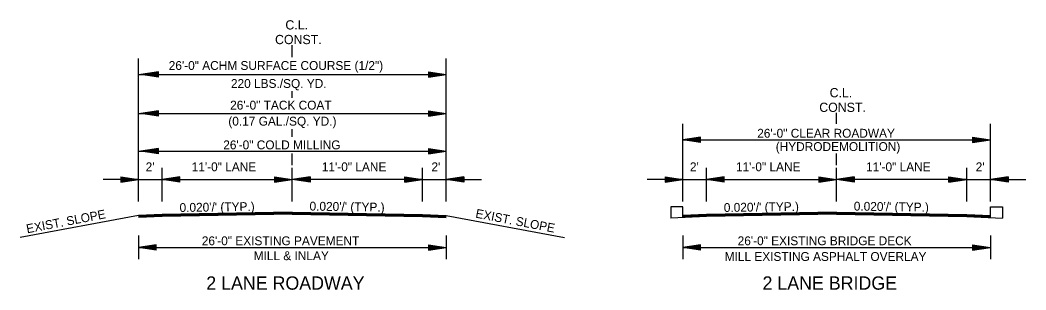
# Model space of a CAD drawing. Extents: x 549600 to 1930787, y -1955432 to 596640.
# Drawn here: x 549615 to 550465, y -1947150 to -1946922 of the extents above; entities that cross this region are included whole.
import ezdxf

# ---------------------------------------------------------------- set-up
doc = ezdxf.new("R2010")
doc.units = 0
doc.layers.add('R_Border', color=7, linetype='Continuous')
doc.layers.add('S_AREA_CALC', color=7, linetype='Continuous')

msp = doc.modelspace()

# ---------------------------------------------------------------- linework, layer by layer
at = {"layer": 'R_Border'}
for p, q in [((549974.89, -1947056.39), (550004.89, -1947056.39)), ((550434.89, -1947056.39), (550464.89, -1947056.39)), ((550164.72, -1947079.69), (550164.71, -1947089.07)), ((550174.89, -1947079.69), (550164.72, -1947079.69)), ((550174.89, -1947088.49), (550174.89, -1947079.69)), ((550434.89, -1947088.49), (550434.89, -1947079.69)), ((550434.89, -1947079.69), (550445.05, -1947079.69)), ((550445.05, -1947079.69), (550445.07, -1947089.07))]:
    msp.add_line(p, q, dxfattribs=at)
at = {"layer": 'S_AREA_CALC'}
for p, q in [((549844.89, -1946953.23), (549844.89, -1946942.86)), ((549714.89, -1947075.21), (549714.89, -1946954.34)), ((549974.89, -1947075.21), (549974.89, -1946954.34)), ((549714.89, -1946967.71), (549974.89, -1946967.71)), ((549731.89, -1946965.46), (549716.89, -1946967.71)), ((549731.89, -1946969.96), (549716.89, -1946967.71)), ((549731.89, -1946965.84), (549719.39, -1946967.71)), ((549731.89, -1946969.59), (549719.39, -1946967.71)), ((549731.89, -1946966.22), (549721.97, -1946967.71)), ((549731.89, -1946969.2), (549721.97, -1946967.71)), ((549731.89, -1946966.59), (549724.47, -1946967.71)), ((549731.89, -1946968.83), (549724.47, -1946967.71)), ((549731.89, -1946966.98), (549727.01, -1946967.71)), ((549731.89, -1946968.44), (549727.01, -1946967.71)), ((549731.89, -1946967.36), (549729.52, -1946967.71)), ((549731.89, -1946968.06), (549729.52, -1946967.71)), ((549731.89, -1946969.96), (549731.89, -1946965.46)), ((549959.89, -1946965.46), (549974.89, -1946967.71)), ((549959.89, -1946965.46), (549959.89, -1946969.96)), ((549959.89, -1946965.84), (549972.38, -1946967.71)), ((549959.89, -1946966.22), (549969.8, -1946967.71)), ((549959.89, -1946966.59), (549967.31, -1946967.71)), ((549959.89, -1946966.98), (549964.76, -1946967.71)), ((549959.89, -1946967.36), (549962.26, -1946967.71)), ((549959.89, -1946969.96), (549974.89, -1946967.71)), ((549959.89, -1946968.45), (549964.76, -1946967.71)), ((549959.89, -1946969.2), (549969.8, -1946967.71)), ((549959.89, -1946969.59), (549972.38, -1946967.71)), ((549959.89, -1946968.83), (549967.31, -1946967.71)), ((549959.89, -1946968.06), (549962.26, -1946967.71)), ((549844.89, -1946987.45), (549844.89, -1946981.92)), ((549714.89, -1947000.68), (549974.89, -1947000.68)), ((549731.89, -1946998.43), (549716.89, -1947000.68)), ((549731.89, -1947002.93), (549716.89, -1947000.68)), ((549731.89, -1946998.8), (549719.39, -1947000.68)), ((549731.89, -1947002.55), (549719.39, -1947000.68)), ((549731.89, -1946999.19), (549721.97, -1947000.68)), ((549731.89, -1947002.17), (549721.97, -1947000.68)), ((549731.89, -1946999.56), (549724.47, -1947000.68)), ((549731.89, -1947001.8), (549724.47, -1947000.68)), ((549731.89, -1946999.94), (549727.01, -1947000.68)), ((549731.89, -1947001.41), (549727.01, -1947000.68)), ((549731.89, -1947000.33), (549729.52, -1947000.68)), ((549731.89, -1947001.03), (549729.52, -1947000.68)), ((549731.89, -1947002.93), (549731.89, -1946998.43)), ((549959.89, -1946998.43), (549974.89, -1947000.68)), ((549959.89, -1946998.43), (549959.89, -1947002.93)), ((549959.89, -1946998.8), (549972.38, -1947000.68)), ((549959.89, -1946999.19), (549969.8, -1947000.68)), ((549959.89, -1946999.56), (549967.31, -1947000.68)), ((549959.89, -1946999.95), (549964.76, -1947000.68)), ((549959.89, -1947000.33), (549962.26, -1947000.68)), ((549959.89, -1947002.93), (549974.89, -1947000.68)), ((549959.89, -1947001.41), (549964.76, -1947000.68)), ((549959.89, -1947002.17), (549969.8, -1947000.68)), ((549959.89, -1947002.55), (549972.38, -1947000.68)), ((549959.89, -1947001.8), (549967.31, -1947000.68)), ((549959.89, -1947001.03), (549962.26, -1947000.68)), ((550304.89, -1947009.43), (550304.89, -1947000.13)), ((549974.89, -1947075.21), (549974.89, -1947009.48)), ((550174.89, -1947075.21), (550174.89, -1947009.48)), ((550434.89, -1947075.21), (550434.89, -1947009.48)), ((549844.89, -1947020.42), (549844.89, -1947014)), ((550189.89, -1947020.6), (550174.89, -1947022.85)), ((550189.89, -1947020.97), (550177.39, -1947022.85)), ((550189.89, -1947021.36), (550179.97, -1947022.85)), ((550189.89, -1947021.73), (550182.47, -1947022.85)), ((550189.89, -1947025.1), (550189.89, -1947020.6)), ((550419.89, -1947020.6), (550434.89, -1947022.85)), ((550419.89, -1947020.6), (550419.89, -1947025.1)), ((550419.89, -1947020.97), (550432.38, -1947022.85)), ((550419.89, -1947021.36), (550429.8, -1947022.85)), ((550419.89, -1947021.73), (550427.31, -1947022.85)), ((550174.89, -1947022.85), (550432.89, -1947022.85)), ((550189.89, -1947025.1), (550174.89, -1947022.85)), ((550189.89, -1947024.72), (550177.39, -1947022.85)), ((550189.89, -1947024.34), (550179.97, -1947022.85)), ((550189.89, -1947023.97), (550182.47, -1947022.85)), ((550189.89, -1947022.11), (550185.01, -1947022.85)), ((550189.89, -1947023.58), (550185.01, -1947022.85)), ((550189.89, -1947022.5), (550187.52, -1947022.85)), ((550189.89, -1947023.2), (550187.52, -1947022.85)), ((550419.89, -1947022.12), (550424.76, -1947022.85)), ((550419.89, -1947022.5), (550422.26, -1947022.85)), ((550419.89, -1947025.1), (550434.89, -1947022.85)), ((550419.89, -1947023.58), (550424.76, -1947022.85)), ((550419.89, -1947024.34), (550429.8, -1947022.85)), ((550419.89, -1947024.72), (550432.38, -1947022.85)), ((550419.89, -1947023.97), (550427.31, -1947022.85)), ((550419.89, -1947023.2), (550422.26, -1947022.85)), ((549714.89, -1947032.65), (549974.89, -1947032.65)), ((549731.89, -1947030.4), (549716.89, -1947032.65)), ((549731.89, -1947034.9), (549716.89, -1947032.65)), ((549731.89, -1947030.78), (549719.39, -1947032.65)), ((549731.89, -1947034.53), (549719.39, -1947032.65)), ((549731.89, -1947031.16), (549721.97, -1947032.65)), ((549731.89, -1947034.14), (549721.97, -1947032.65)), ((549731.89, -1947031.53), (549724.47, -1947032.65)), ((549731.89, -1947033.77), (549724.47, -1947032.65)), ((549731.89, -1947031.92), (549727.01, -1947032.65)), ((549731.89, -1947033.38), (549727.01, -1947032.65)), ((549731.89, -1947032.3), (549729.52, -1947032.65)), ((549731.89, -1947033), (549729.52, -1947032.65)), ((549731.89, -1947034.9), (549731.89, -1947030.4)), ((549844.89, -1947044.37), (549844.89, -1947034.5)), ((549959.89, -1947030.4), (549974.89, -1947032.65)), ((549959.89, -1947030.4), (549959.89, -1947034.9)), ((549959.89, -1947030.78), (549972.38, -1947032.65)), ((549959.89, -1947031.16), (549969.8, -1947032.65)), ((549959.89, -1947031.53), (549967.31, -1947032.65)), ((549959.89, -1947031.92), (549964.76, -1947032.65)), ((549959.89, -1947032.3), (549962.26, -1947032.65)), ((549959.89, -1947034.9), (549974.89, -1947032.65)), ((549959.89, -1947033.39), (549964.76, -1947032.65)), ((549959.89, -1947034.14), (549969.8, -1947032.65)), ((549959.89, -1947034.53), (549972.38, -1947032.65)), ((549959.89, -1947033.77), (549967.31, -1947032.65)), ((549959.89, -1947033), (549962.26, -1947032.65)), ((550304.89, -1947044.37), (550304.89, -1947034.5)), ((549734.89, -1947075.21), (549734.89, -1947046.49)), ((549844.89, -1947075.04), (549844.89, -1947046.49)), ((549954.89, -1947075.21), (549954.89, -1947046.49)), ((550194.89, -1947075.21), (550194.89, -1947046.49)), ((550304.89, -1947075.04), (550304.89, -1947046.49)), ((550414.89, -1947075.21), (550414.89, -1947046.49)), ((549699.89, -1947054.14), (549714.89, -1947056.39)), ((549699.89, -1947054.14), (549699.89, -1947058.64)), ((549699.89, -1947054.51), (549712.38, -1947056.39)), ((549699.89, -1947054.89), (549709.8, -1947056.39)), ((549699.89, -1947055.27), (549707.31, -1947056.39)), ((549699.89, -1947055.66), (549704.76, -1947056.39)), ((549749.89, -1947054.14), (549734.89, -1947056.39)), ((549749.89, -1947054.51), (549737.39, -1947056.39)), ((549749.89, -1947054.89), (549739.97, -1947056.39)), ((549749.89, -1947055.27), (549742.47, -1947056.39)), ((549749.89, -1947055.65), (549745.01, -1947056.39)), ((549749.89, -1947058.64), (549749.89, -1947054.14)), ((549829.89, -1947054.14), (549844.89, -1947056.39)), ((549829.89, -1947054.14), (549829.89, -1947058.64)), ((549829.89, -1947054.51), (549842.38, -1947056.39)), ((549829.89, -1947054.89), (549839.8, -1947056.39)), ((549829.89, -1947055.27), (549837.31, -1947056.39)), ((549829.89, -1947055.66), (549834.76, -1947056.39)), ((549859.89, -1947054.14), (549844.89, -1947056.39)), ((549859.89, -1947054.51), (549847.39, -1947056.39)), ((549859.89, -1947054.89), (549849.97, -1947056.39)), ((549859.89, -1947055.27), (549852.47, -1947056.39)), ((549859.89, -1947055.66), (549855.01, -1947056.39)), ((549859.89, -1947054.14), (549859.89, -1947058.64)), ((549939.89, -1947054.14), (549954.89, -1947056.39)), ((549939.89, -1947058.64), (549939.89, -1947054.14)), ((549939.89, -1947054.51), (549952.38, -1947056.39)), ((549939.89, -1947054.89), (549949.8, -1947056.39)), ((549939.89, -1947055.27), (549947.31, -1947056.39)), ((549939.89, -1947055.65), (549944.76, -1947056.39)), ((549989.89, -1947054.14), (549974.89, -1947056.39)), ((549989.89, -1947054.51), (549977.39, -1947056.39)), ((549989.89, -1947054.89), (549979.97, -1947056.39)), ((549989.89, -1947055.27), (549982.47, -1947056.39)), ((549989.89, -1947055.66), (549985.01, -1947056.39)), ((549989.89, -1947054.14), (549989.89, -1947058.64)), ((550159.89, -1947054.14), (550174.89, -1947056.39)), ((550159.89, -1947054.14), (550159.89, -1947058.64)), ((550159.89, -1947054.51), (550172.38, -1947056.39)), ((550159.89, -1947054.89), (550169.8, -1947056.39)), ((550159.89, -1947055.27), (550167.31, -1947056.39)), ((550159.89, -1947055.66), (550164.76, -1947056.39)), ((550209.89, -1947054.14), (550194.89, -1947056.39)), ((550209.89, -1947054.51), (550197.39, -1947056.39)), ((550209.89, -1947054.89), (550199.97, -1947056.39)), ((550209.89, -1947055.27), (550202.47, -1947056.39)), ((550209.89, -1947055.65), (550205.01, -1947056.39)), ((550209.89, -1947058.64), (550209.89, -1947054.14)), ((550289.89, -1947054.14), (550304.89, -1947056.39)), ((550289.89, -1947054.14), (550289.89, -1947058.64)), ((550289.89, -1947054.51), (550302.38, -1947056.39)), ((550289.89, -1947054.89), (550299.8, -1947056.39)), ((550289.89, -1947055.27), (550297.31, -1947056.39)), ((550289.89, -1947055.66), (550294.76, -1947056.39)), ((550319.89, -1947054.14), (550304.89, -1947056.39)), ((550319.89, -1947054.51), (550307.39, -1947056.39)), ((550319.89, -1947054.89), (550309.97, -1947056.39)), ((550319.89, -1947055.27), (550312.47, -1947056.39)), ((550319.89, -1947055.66), (550315.01, -1947056.39)), ((550319.89, -1947054.14), (550319.89, -1947058.64)), ((550399.89, -1947054.14), (550414.89, -1947056.39)), ((550399.89, -1947058.64), (550399.89, -1947054.14)), ((550399.89, -1947054.51), (550412.38, -1947056.39)), ((550399.89, -1947054.89), (550409.8, -1947056.39)), ((550399.89, -1947055.27), (550407.31, -1947056.39)), ((550399.89, -1947055.65), (550404.76, -1947056.39)), ((550449.89, -1947054.14), (550434.89, -1947056.39)), ((550449.89, -1947054.51), (550437.39, -1947056.39)), ((550449.89, -1947054.89), (550439.97, -1947056.39)), ((550449.89, -1947055.27), (550442.47, -1947056.39)), ((550449.89, -1947055.66), (550445.01, -1947056.39)), ((550449.89, -1947054.14), (550449.89, -1947058.64)), ((549714.89, -1947056.39), (549684.89, -1947056.39)), ((549699.89, -1947056.03), (549702.26, -1947056.39)), ((549699.89, -1947058.64), (549714.89, -1947056.39)), ((549699.89, -1947057.12), (549704.76, -1947056.39)), ((549699.89, -1947057.88), (549709.8, -1947056.39)), ((549699.89, -1947058.26), (549712.38, -1947056.39)), ((549699.89, -1947057.5), (549707.31, -1947056.39)), ((549699.89, -1947056.74), (549702.26, -1947056.39)), ((549714.89, -1947056.39), (549734.89, -1947056.39)), ((549749.89, -1947058.64), (549734.89, -1947056.39)), ((549734.89, -1947056.39), (549844.89, -1947056.39)), ((549749.89, -1947058.26), (549737.39, -1947056.39)), ((549749.89, -1947057.88), (549739.97, -1947056.39)), ((549749.89, -1947057.5), (549742.47, -1947056.39)), ((549749.89, -1947057.11), (549745.01, -1947056.39)), ((549749.89, -1947056.03), (549747.52, -1947056.39)), ((549749.89, -1947056.74), (549747.52, -1947056.39)), ((549829.89, -1947056.03), (549832.26, -1947056.39)), ((549829.89, -1947058.64), (549844.89, -1947056.39)), ((549829.89, -1947057.12), (549834.76, -1947056.39)), ((549829.89, -1947057.88), (549839.8, -1947056.39)), ((549829.89, -1947058.26), (549842.38, -1947056.39)), ((549829.89, -1947057.5), (549837.31, -1947056.39)), ((549829.89, -1947056.74), (549832.26, -1947056.39)), ((549954.89, -1947056.39), (549844.89, -1947056.39)), ((549859.89, -1947058.64), (549844.89, -1947056.39)), ((549859.89, -1947058.26), (549847.39, -1947056.39)), ((549859.89, -1947057.88), (549849.97, -1947056.39)), ((549859.89, -1947057.5), (549852.47, -1947056.39)), ((549859.89, -1947057.12), (549855.01, -1947056.39)), ((549859.89, -1947056.03), (549857.52, -1947056.39)), ((549859.89, -1947056.74), (549857.52, -1947056.39)), ((549939.89, -1947056.03), (549942.26, -1947056.39)), ((549939.89, -1947058.64), (549954.89, -1947056.39)), ((549939.89, -1947057.11), (549944.76, -1947056.39)), ((549939.89, -1947057.88), (549949.8, -1947056.39)), ((549939.89, -1947058.26), (549952.38, -1947056.39)), ((549939.89, -1947057.5), (549947.31, -1947056.39)), ((549939.89, -1947056.74), (549942.26, -1947056.39)), ((549954.89, -1947056.39), (549974.89, -1947056.39)), ((549989.89, -1947058.64), (549974.89, -1947056.39)), ((549989.89, -1947058.26), (549977.39, -1947056.39)), ((549989.89, -1947057.88), (549979.97, -1947056.39)), ((549989.89, -1947057.5), (549982.47, -1947056.39)), ((549989.89, -1947057.12), (549985.01, -1947056.39)), ((549989.89, -1947056.03), (549987.52, -1947056.39)), ((549989.89, -1947056.74), (549987.52, -1947056.39)), ((550174.89, -1947056.39), (550144.89, -1947056.39)), ((550159.89, -1947056.03), (550162.26, -1947056.39)), ((550159.89, -1947058.64), (550174.89, -1947056.39)), ((550159.89, -1947057.12), (550164.76, -1947056.39)), ((550159.89, -1947057.88), (550169.8, -1947056.39)), ((550159.89, -1947058.26), (550172.38, -1947056.39)), ((550159.89, -1947057.5), (550167.31, -1947056.39)), ((550159.89, -1947056.74), (550162.26, -1947056.39)), ((550174.89, -1947056.39), (550194.89, -1947056.39)), ((550209.89, -1947058.64), (550194.89, -1947056.39)), ((550194.89, -1947056.39), (550304.89, -1947056.39)), ((550209.89, -1947058.26), (550197.39, -1947056.39)), ((550209.89, -1947057.88), (550199.97, -1947056.39)), ((550209.89, -1947057.5), (550202.47, -1947056.39)), ((550209.89, -1947057.11), (550205.01, -1947056.39)), ((550209.89, -1947056.03), (550207.52, -1947056.39)), ((550209.89, -1947056.74), (550207.52, -1947056.39)), ((550289.89, -1947056.03), (550292.26, -1947056.39)), ((550289.89, -1947058.64), (550304.89, -1947056.39)), ((550289.89, -1947057.12), (550294.76, -1947056.39)), ((550289.89, -1947057.88), (550299.8, -1947056.39)), ((550289.89, -1947058.26), (550302.38, -1947056.39)), ((550289.89, -1947057.5), (550297.31, -1947056.39)), ((550289.89, -1947056.74), (550292.26, -1947056.39)), ((550414.89, -1947056.39), (550304.89, -1947056.39)), ((550319.89, -1947058.64), (550304.89, -1947056.39)), ((550319.89, -1947058.26), (550307.39, -1947056.39)), ((550319.89, -1947057.88), (550309.97, -1947056.39)), ((550319.89, -1947057.5), (550312.47, -1947056.39)), ((550319.89, -1947057.12), (550315.01, -1947056.39)), ((550319.89, -1947056.03), (550317.52, -1947056.39)), ((550319.89, -1947056.74), (550317.52, -1947056.39)), ((550399.89, -1947056.03), (550402.26, -1947056.39)), ((550399.89, -1947058.64), (550414.89, -1947056.39)), ((550399.89, -1947057.11), (550404.76, -1947056.39)), ((550399.89, -1947057.88), (550409.8, -1947056.39)), ((550399.89, -1947058.26), (550412.38, -1947056.39)), ((550399.89, -1947057.5), (550407.31, -1947056.39)), ((550399.89, -1947056.74), (550402.26, -1947056.39)), ((550414.89, -1947056.39), (550434.89, -1947056.39)), ((550449.89, -1947058.64), (550434.89, -1947056.39)), ((550449.89, -1947058.26), (550437.39, -1947056.39)), ((550449.89, -1947057.88), (550439.97, -1947056.39)), ((550449.89, -1947057.5), (550442.47, -1947056.39)), ((550449.89, -1947057.12), (550445.01, -1947056.39)), ((550449.89, -1947056.03), (550447.52, -1947056.39)), ((550449.89, -1947056.74), (550447.52, -1947056.39)), ((549714.89, -1947086.99), (549614.82, -1947105.37)), ((549734.89, -1947086.19), (549714.89, -1947086.99)), ((549734.89, -1947086.49), (549714.89, -1947087.29)), ((549734.89, -1947086.79), (549714.89, -1947087.59)), ((549734.89, -1947087.09), (549714.89, -1947087.89)), ((549734.89, -1947087.39), (549714.89, -1947088.19)), ((549734.89, -1947087.69), (549714.89, -1947088.49)), ((549734.89, -1947087.86), (549714.89, -1947088.66)), ((549844.89, -1947083.99), (549734.89, -1947086.19)), ((549844.89, -1947084.29), (549734.89, -1947086.49)), ((549844.9, -1947084.59), (549734.89, -1947086.79)), ((549844.91, -1947084.89), (549734.89, -1947087.09)), ((549844.91, -1947085.19), (549734.89, -1947087.39)), ((549844.92, -1947085.49), (549734.89, -1947087.69)), ((549844.92, -1947085.66), (549734.89, -1947087.86)), ((549844.85, -1947085.66), (549954.89, -1947087.86)), ((549844.86, -1947085.19), (549954.89, -1947087.39)), ((549844.86, -1947085.49), (549954.89, -1947087.69)), ((549844.87, -1947084.89), (549954.89, -1947087.09)), ((549844.88, -1947084.29), (549954.89, -1947086.49)), ((549844.88, -1947084.59), (549954.89, -1947086.79)), ((549844.89, -1947083.99), (549954.89, -1947086.19)), ((549954.89, -1947086.19), (549974.89, -1947086.99)), ((549954.89, -1947086.49), (549974.89, -1947087.29)), ((549954.89, -1947086.79), (549974.89, -1947087.59)), ((549954.89, -1947087.09), (549974.89, -1947087.89)), ((549954.89, -1947087.39), (549974.89, -1947088.19)), ((549954.89, -1947087.69), (549974.89, -1947088.49)), ((549954.89, -1947087.86), (549974.89, -1947088.66)), ((549974.89, -1947086.99), (550074.96, -1947105.37)), ((550194.89, -1947087.86), (550164.71, -1947089.07)), ((550194.89, -1947086.19), (550174.89, -1947086.99)), ((550194.89, -1947086.49), (550174.89, -1947087.29)), ((550194.89, -1947086.79), (550174.89, -1947087.59)), ((550194.89, -1947087.09), (550174.89, -1947087.89)), ((550194.89, -1947087.39), (550174.89, -1947088.19)), ((550194.89, -1947087.69), (550174.89, -1947088.49)), ((550304.89, -1947083.99), (550194.89, -1947086.19)), ((550304.89, -1947084.29), (550194.89, -1947086.49)), ((550304.9, -1947084.59), (550194.89, -1947086.79)), ((550304.91, -1947084.89), (550194.89, -1947087.09)), ((550304.91, -1947085.19), (550194.89, -1947087.39)), ((550304.92, -1947085.49), (550194.89, -1947087.69)), ((550304.92, -1947085.66), (550194.89, -1947087.86)), ((550304.85, -1947085.66), (550414.89, -1947087.86)), ((550304.86, -1947085.19), (550414.89, -1947087.39)), ((550304.86, -1947085.49), (550414.89, -1947087.69)), ((550304.87, -1947084.89), (550414.89, -1947087.09)), ((550304.88, -1947084.29), (550414.89, -1947086.49)), ((550304.88, -1947084.59), (550414.89, -1947086.79)), ((550304.89, -1947083.99), (550414.89, -1947086.19)), ((550414.89, -1947086.19), (550434.89, -1947086.99)), ((550414.89, -1947086.49), (550434.89, -1947087.29)), ((550414.89, -1947086.79), (550434.89, -1947087.59)), ((550414.89, -1947087.09), (550434.89, -1947087.89)), ((550414.89, -1947087.39), (550434.89, -1947088.19)), ((550414.89, -1947087.69), (550434.89, -1947088.49)), ((550414.89, -1947087.86), (550445.07, -1947089.07)), ((549714.89, -1947103.85), (549714.89, -1947123.85)), ((549974.89, -1947103.85), (549974.89, -1947123.85)), ((550174.89, -1947103.85), (550174.89, -1947123.85)), ((550434.89, -1947103.85), (550434.89, -1947123.85)), ((549729.89, -1947111.6), (549714.89, -1947113.85)), ((549714.89, -1947113.85), (549974.89, -1947113.85)), ((549729.89, -1947116.1), (549714.89, -1947113.85)), ((549729.89, -1947111.98), (549717.39, -1947113.85)), ((549729.89, -1947115.73), (549717.39, -1947113.85)), ((549729.89, -1947112.36), (549719.97, -1947113.85)), ((549729.89, -1947115.34), (549719.97, -1947113.85)), ((549729.89, -1947112.73), (549722.47, -1947113.85)), ((549729.89, -1947114.97), (549722.47, -1947113.85)), ((549729.89, -1947113.12), (549725.01, -1947113.85)), ((549729.89, -1947114.58), (549725.01, -1947113.85)), ((549729.89, -1947113.5), (549727.52, -1947113.85)), ((549729.89, -1947114.2), (549727.52, -1947113.85)), ((549729.89, -1947116.1), (549729.89, -1947111.6)), ((549959.89, -1947111.6), (549974.89, -1947113.85)), ((549959.89, -1947111.6), (549959.89, -1947116.1)), ((549959.89, -1947111.98), (549972.38, -1947113.85)), ((549959.89, -1947112.36), (549969.8, -1947113.85)), ((549959.89, -1947112.73), (549967.31, -1947113.85)), ((549959.89, -1947113.12), (549964.76, -1947113.85)), ((549959.89, -1947113.5), (549962.26, -1947113.85)), ((549959.89, -1947116.1), (549974.89, -1947113.85)), ((549959.89, -1947114.59), (549964.76, -1947113.85)), ((549959.89, -1947115.34), (549969.8, -1947113.85)), ((549959.89, -1947115.73), (549972.38, -1947113.85)), ((549959.89, -1947114.97), (549967.31, -1947113.85)), ((549959.89, -1947114.2), (549962.26, -1947113.85)), ((550189.89, -1947111.6), (550174.89, -1947113.85)), ((550174.89, -1947113.85), (550434.89, -1947113.85)), ((550189.89, -1947116.1), (550174.89, -1947113.85)), ((550189.89, -1947111.98), (550177.39, -1947113.85)), ((550189.89, -1947115.73), (550177.39, -1947113.85)), ((550189.89, -1947112.36), (550179.97, -1947113.85)), ((550189.89, -1947115.34), (550179.97, -1947113.85)), ((550189.89, -1947112.73), (550182.47, -1947113.85)), ((550189.89, -1947114.97), (550182.47, -1947113.85)), ((550189.89, -1947113.12), (550185.01, -1947113.85)), ((550189.89, -1947114.58), (550185.01, -1947113.85)), ((550189.89, -1947113.5), (550187.52, -1947113.85)), ((550189.89, -1947114.2), (550187.52, -1947113.85)), ((550189.89, -1947116.1), (550189.89, -1947111.6)), ((550419.89, -1947111.6), (550434.89, -1947113.85)), ((550419.89, -1947111.6), (550419.89, -1947116.1)), ((550419.89, -1947111.98), (550432.38, -1947113.85)), ((550419.89, -1947112.36), (550429.8, -1947113.85)), ((550419.89, -1947112.73), (550427.31, -1947113.85)), ((550419.89, -1947113.12), (550424.76, -1947113.85)), ((550419.89, -1947113.5), (550422.26, -1947113.85)), ((550419.89, -1947116.1), (550434.89, -1947113.85)), ((550419.89, -1947114.59), (550424.76, -1947113.85)), ((550419.89, -1947115.34), (550429.8, -1947113.85)), ((550419.89, -1947115.73), (550432.38, -1947113.85)), ((550419.89, -1947114.97), (550427.31, -1947113.85)), ((550419.89, -1947114.2), (550422.26, -1947113.85))]:
    msp.add_line(p, q, dxfattribs=at)

# ---------------------------------------------------------------- texts
for s, height, p in [('C.L.', 7.8, (549839.04, -1946929.76)), ('CONST.', 7.8, (549830.26, -1946942.13)), ('26\'-0" ACHM SURFACE COURSE (1/2")', 7.5, (549740.42, -1946963.94)), ('220 LBS./SQ. YD. ', 7.5, (549793.01, -1946979.13)), ('C.L.', 7.8, (550299.04, -1946987.04)), ('26\'-0" TACK COAT', 7.5, (549792.36, -1946997.41)), ('CONST.', 7.8, (550290.26, -1946999.4)), ('(0.17 GAL./SQ. YD.)', 7.5, (549790.8, -1947010.96)), ('26\'-0" CLEAR ROADWAY ', 7.5, (550237.8, -1947021.18)), ('26\'-0" COLD MILLING ', 7.5, (549786.51, -1947030.98)), ('(HYDRODEMOLITION)', 7.5, (550253.45, -1947032.43)), ("2'", 7.5, (549720.93, -1947049.52)), ('11\'-0" LANE', 7.5, (549759.83, -1947049.52)), ('11\'-0" LANE', 7.5, (549869.83, -1947049.52)), ("2'", 7.5, (549962.49, -1947049.52)), ("2'", 7.5, (550180.93, -1947049.52)), ('11\'-0" LANE', 7.5, (550219.83, -1947049.52)), ('11\'-0" LANE', 7.5, (550329.83, -1947049.52)), ("2'", 7.5, (550422.49, -1947049.52)), ('26\'-0" EXISTING PAVEMENT', 7.5, (549768.38, -1947112.02)), ('26\'-0" EXISTING BRIDGE DECK', 7.5, (550221.27, -1947112.02)), ('MILL & INLAY', 7.5, (549812.21, -1947124.63)), ('MILL EXISTING ASPHALT OVERLAY', 7.5, (550210.31, -1947125.29)), ('2 LANE ROADWAY', 11.25, (549772.16, -1947149.57)), ('2 LANE BRIDGE', 11.25, (550242.29, -1947149.57))]:
    msp.add_text(s, height=height, dxfattribs=at).set_placement(p)
for s, rotation, p in [("0.020'/' (TYP.)", 0.87191, (549749.63, -1947083.95)), ("0.020'/' (TYP.)", 359.12809, (549859.38, -1947082.72)), ('EXIST. SLOPE', 349.11714, (549999.27, -1947088.59)), ("0.020'/' (TYP.)", 0.87191, (550209.63, -1947083.95)), ("0.020'/' (TYP.)", 359.12809, (550319.38, -1947082.72)), ('EXIST. SLOPE', 10.88286, (549620.8, -1947101.99))]:
    msp.add_text(s, height=7.5, rotation=rotation, dxfattribs=at).set_placement(p)

doc.saveas('drawing.dxf')
